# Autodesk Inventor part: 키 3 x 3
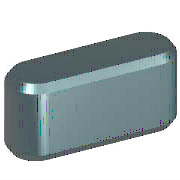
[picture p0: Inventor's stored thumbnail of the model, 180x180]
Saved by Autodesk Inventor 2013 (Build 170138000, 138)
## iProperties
Created: 2012-02
Part Number: 키 3 x 3
Material: 강철, 연강
Description: 키 및 해당 키홈
Document SubType Name: Modeling
Standard: KS B 1311
Designer: mduedu
Standards Organization: KS
Language: ko-KR
Size Designation: 3 x 3 x 12
Categories: <MemberInstance><Categories><Category DisplayName="샤프트 부품" InternalName="7f7aeb1f-a693-4053-b835-cee3144e0d98" Mnemonic="SHFT"><Category DisplayName="키" Interna
Density: 7.86 g/cm^3
Mass: 0.790122 g
Surface Area: 1.42216 cm^2
Volume: 0.100524 cm^3
IsCustomPart: 1
Author: mduedu
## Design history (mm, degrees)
workplane "Work Plane1"
workplane "Work Plane2"
sketch "스케치1"
  geometry: L1 (1.5, 1.5)-(10.5, 1.5); L2 (10.5, -1.5)-(1.5, -1.5); L3 (0, 9.4)-(0, -7.4) reference; L4 (-5, 0)-(30, 0) reference; L5 (12, 0)-(12, 7); A1 r 1.5 centre (1.5, 0) between (1.5, 1.5) and (1.5, -1.5); A2 r 1.5 centre (10.5, 0) between (10.5, -1.5) and (10.5, 1.5)
  constraints: 6 end point, 5 point on circle, 4 tangent, 3 point on line, 2 centre point, 1 horizontal, 1 parallel, 1 perpendicular
  dimensions: "d0" = 1.5 radius of A1 (= 0.5 x PB); "d13" = 1.5 radius of A2 (= 0.5 x PB); "d14" = 12 distance between parallel lines of L5 L3 (= NLG)
extrude "본체1" new body sketch "스케치1" taper "d3" = 0 deg; stored distance "d4" = 10
workplane "Work Plane3"
body "Solid1"
chamfer "모따기1" distance "d8" = 0.25 (= PHH); stored, may be unused: second distance "d9" = 0.25 (= PHH), angle "d15" = 45 deg
other parameters: "d1" = -1.8 (= -PNT), "d2" = 1.2 (= PH - PNT), "NLG" = 12 [user parameter; used in 3 equation terms], "PB" = 3 [user parameter; used in 2 equation terms], "PNT" = 1.8 [user parameter; used in 2 equation terms], "PH" = 3 [user parameter; used in 1 equation term], "PHH" = 0.25 [user parameter; used in 2 equation terms], "d10" = 0, "d16" = 0, "d17" = 0, "d18" = 0, "WDMIN" = 8 [user parameter], "PLB2" = 12 (= NLG) [user parameter], "PLB1" = 12 (= NLG) [user parameter], "RR" = 0.08 [user parameter], "PUEB" = 1.4 [user parameter]
